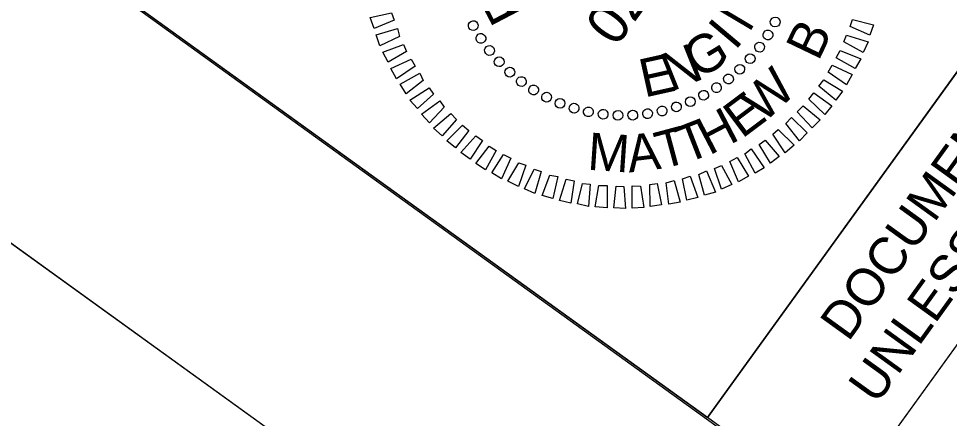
# Model space of a CAD drawing. Extents: x 2189185 to 2191058, y 386509 to 388561.
# Drawn here: x 2190081.4 to 2190218.6, y 388238.4 to 388297.3 of the extents above; entities that cross this region are included whole.
import ezdxf

# ---------------------------------------------------------------- set-up
doc = ezdxf.new("R2010")
doc.units = 0
for name, color, linetype in [('Sheet Clip Boundary CELL', 7, 'Continuous'), ('Sheet Layout Plan Border', 7, 'Continuous'), ('Sheet Plan CELL', 7, 'Continuous'), ('Sheet Plan Layout CELL', 7, 'Continuous'), ('Sheet Professional Seal CELL', 7, 'Continuous'), ('Sheet Sticker Exception Certification CELL', 7, 'Continuous')]:
    doc.layers.add(name, color=color, linetype=linetype)

msp = doc.modelspace()

# ---------------------------------------------------------------- linework, layer by layer
at = {"layer": 'Sheet Clip Boundary CELL'}
msp.add_lwpolyline([(2190166.8, 386710.01), (2190905.33, 387738.93), (2190256.9, 388232.77), (2190233.39, 388201.76), (2190061.07, 388326.03), (2189853.58, 388001.31), (2189912.61, 387915.43), (2189757.61, 387710.51), (2189654.64, 387750.49), (2189330.08, 387312.42)], close=True, dxfattribs=at)
at = {"layer": 'Sheet Layout Plan Border'}
msp.add_lwpolyline([(2190181.72, 386698.24), (2191000.63, 387833.76), (2190320.53, 388324.24), (2190209.82, 388170.73), (2190038.29, 388294.44), (2189330.08, 387312.42)], close=True, dxfattribs=at)
at = {"layer": 'Sheet Plan CELL'}
for points in [[(2190152.47, 386657.68), (2189300.84, 387271.83), (2190061.21, 388326.25), (2190182.93, 388238.48), (2190299.95, 388400.72), (2191029.88, 387874.32)], [(2190091.69, 388304.27), (2190150.21, 388385.42), (2190241.47, 388319.6), (2190182.93, 388238.48)]]:
    msp.add_lwpolyline(points, close=True, dxfattribs=at)
at = {"layer": 'Sheet Plan Layout CELL'}
for points in [[(2190209.82, 388170.73), (2190349.78, 388364.8), (2190178.26, 388488.53), (2190038.29, 388294.44)], [(2189300.84, 387271.83), (2190152.47, 386657.68), (2191029.87, 387874.31), (2190349.77, 388364.78), (2190209.82, 388170.73), (2190038.29, 388294.44)]]:
    msp.add_lwpolyline(points, close=True, dxfattribs=at)
at = {"layer": 'Sheet Professional Seal CELL'}
for p, q in [((2190148.38, 388296.22), (2190148.38, 388296.22)), ((2190192.85, 388296.77), (2190192.85, 388296.77)), ((2190191.83, 388294.85), (2190191.83, 388294.85)), ((2190149.48, 388294.32), (2190149.48, 388294.32)), ((2190150.77, 388292.53), (2190150.77, 388292.53)), ((2190190.59, 388293.03), (2190190.59, 388293.03)), ((2190152.21, 388290.94), (2190152.21, 388290.94)), ((2190189.18, 388291.34), (2190189.18, 388291.34)), ((2190153.75, 388289.39), (2190153.75, 388289.39)), ((2190187.64, 388289.8), (2190187.64, 388289.8)), ((2190155.45, 388287.99), (2190155.45, 388287.99)), ((2190186.04, 388288.36), (2190186.04, 388288.36)), ((2190157.26, 388286.74), (2190157.26, 388286.74)), ((2190184.25, 388287.06), (2190184.25, 388287.06)), ((2190159.18, 388285.72), (2190159.18, 388285.72)), ((2190182.35, 388285.97), (2190182.35, 388285.97)), ((2190161.2, 388284.76), (2190161.2, 388284.76)), ((2190163.25, 388284.02), (2190163.25, 388284.02)), ((2190178.33, 388284.24), (2190178.33, 388284.24)), ((2190180.4, 388284.97), (2190180.4, 388284.97)), ((2190165.34, 388283.5), (2190165.34, 388283.5)), ((2190167.51, 388283.17), (2190167.51, 388283.17)), ((2190169.72, 388282.99), (2190169.72, 388282.99)), ((2190171.87, 388282.98), (2190171.87, 388282.98)), ((2190174.09, 388283.23), (2190174.09, 388283.23)), ((2190176.21, 388283.61), (2190176.21, 388283.61))]:
    msp.add_line(p, q, dxfattribs=at)
for points in [[(2190136.75, 388297.03), (2190133.8, 388295.83), (2190133.17, 388297.45), (2190136.36, 388298.11)], [(2190204.28, 388297.15), (2190207.39, 388296.33), (2190206.85, 388294.81), (2190203.95, 388296.09)], [(2190137.5, 388294.64), (2190134.64, 388293.25), (2190134.09, 388294.88), (2190137.24, 388295.82)], [(2190203.41, 388294.82), (2190206.58, 388293.83), (2190205.86, 388292.25), (2190202.99, 388293.83)], [(2190138.54, 388292.41), (2190135.86, 388290.83), (2190135.04, 388292.34), (2190138.12, 388293.45)], [(2190202.45, 388292.56), (2190205.51, 388291.33), (2190204.67, 388289.91), (2190201.87, 388291.49)], [(2190139.82, 388290.25), (2190137.07, 388288.41), (2190136.26, 388289.93), (2190139.22, 388291.3)], [(2190201.29, 388290.43), (2190204.21, 388289.01), (2190203.37, 388287.51), (2190200.71, 388289.37)], [(2190141.02, 388288.16), (2190138.48, 388286.17), (2190137.6, 388287.6), (2190140.49, 388289.22)], [(2190200.03, 388288.26), (2190202.81, 388286.56), (2190201.8, 388285.25), (2190199.29, 388287.31)], [(2190142.53, 388286.14), (2190140.19, 388284.01), (2190139.05, 388285.26), (2190141.91, 388287.08)], [(2190198.58, 388286.34), (2190201.22, 388284.44), (2190200.21, 388283.13), (2190197.84, 388285.4)], [(2190144.09, 388284.21), (2190141.96, 388281.93), (2190140.78, 388283.21), (2190143.48, 388285.15)], [(2190197, 388284.4), (2190199.52, 388282.34), (2190198.31, 388281.18), (2190196.14, 388283.55)], [(2190145.93, 388282.4), (2190143.81, 388279.98), (2190142.55, 388281.13), (2190145.1, 388283.3)], [(2190195.27, 388282.69), (2190197.6, 388280.45), (2190196.44, 388279.26), (2190194.45, 388281.8)], [(2190147.73, 388280.79), (2190145.75, 388278.21), (2190144.47, 388279.26), (2190146.81, 388281.57)], [(2190149.73, 388279.29), (2190147.95, 388276.56), (2190146.57, 388277.56), (2190148.75, 388279.99)], [(2190193.33, 388280.94), (2190195.68, 388278.64), (2190194.36, 388277.49), (2190192.52, 388280.24)], [(2190151.78, 388277.86), (2190150.21, 388274.99), (2190148.77, 388275.91), (2190150.75, 388278.49)], [(2190191.4, 388279.38), (2190193.48, 388276.95), (2190192.17, 388275.99), (2190190.5, 388278.73)], [(2190153.91, 388276.7), (2190152.57, 388273.66), (2190151.11, 388274.53), (2190152.82, 388277.24)], [(2190189.36, 388278.08), (2190191.24, 388275.3), (2190189.93, 388274.52), (2190188.4, 388277.35)], [(2190156.12, 388275.67), (2190155.04, 388272.55), (2190153.49, 388273.31), (2190155.09, 388276.04)], [(2190184.99, 388275.62), (2190186.51, 388272.85), (2190184.95, 388272.13), (2190183.95, 388275.2)], [(2190187.27, 388276.81), (2190188.93, 388274.07), (2190187.46, 388273.22), (2190186.18, 388276.24)], [(2190158.41, 388274.75), (2190157.47, 388271.48), (2190155.96, 388272.2), (2190157.36, 388275.08)], [(2190160.83, 388273.99), (2190160.1, 388270.76), (2190158.52, 388271.22), (2190159.68, 388274.2)], [(2190182.76, 388274.82), (2190184.09, 388271.71), (2190182.47, 388271.27), (2190181.63, 388274.28)], [(2190163.26, 388273.35), (2190162.75, 388270.08), (2190161.07, 388270.49), (2190162.08, 388273.59)], [(2190165.59, 388272.9), (2190165.37, 388269.61), (2190163.73, 388269.99), (2190164.47, 388272.97)], [(2190175.5, 388272.97), (2190176.15, 388269.85), (2190174.47, 388269.58), (2190174.41, 388272.83)], [(2190177.97, 388273.4), (2190178.88, 388270.22), (2190177.21, 388269.95), (2190176.81, 388273.07)], [(2190180.34, 388274.04), (2190181.49, 388270.93), (2190179.84, 388270.52), (2190179.22, 388273.68)], [(2190168.13, 388272.67), (2190168.13, 388269.41), (2190166.35, 388269.52), (2190166.91, 388272.69)], [(2190170.56, 388272.53), (2190170.83, 388269.31), (2190169.1, 388269.39), (2190169.44, 388272.59)], [(2190173.02, 388272.6), (2190173.5, 388269.42), (2190171.79, 388269.36), (2190171.8, 388272.62)]]:
    msp.add_lwpolyline(points, close=True, dxfattribs=at)
for centre, major_axis in [((2190192.88, 388296.77), (0.643, -0.325)), ((2190148.39, 388296.23), (-0.635, -0.34)), ((2190149.51, 388294.35), (-0.602, -0.394)), ((2190191.81, 388294.86), (0.612, -0.379)), ((2190190.58, 388293.06), (0.577, -0.431)), ((2190150.78, 388292.57), (-0.566, -0.445)), ((2190189.19, 388291.36), (0.537, -0.48)), ((2190152.21, 388290.91), (-0.525, -0.493)), ((2190153.78, 388289.38), (-0.48, -0.537)), ((2190187.66, 388289.8), (0.493, -0.525)), ((2190155.47, 388288), (-0.431, -0.577)), ((2190184.23, 388287.09), (0.394, -0.602)), ((2190186, 388288.37), (0.445, -0.566)), ((2190157.28, 388286.76), (-0.379, -0.612)), ((2190182.34, 388285.98), (0.34, -0.635)), ((2190159.19, 388285.69), (-0.325, -0.643)), ((2190161.18, 388284.79), (-0.267, -0.669)), ((2190180.37, 388285.03), (0.284, -0.662)), ((2190163.24, 388284.07), (-0.208, -0.689)), ((2190165.36, 388283.53), (-0.147, -0.705)), ((2190167.52, 388283.18), (-0.085, -0.715)), ((2190174.07, 388283.26), (0.103, -0.713)), ((2190176.22, 388283.66), (0.164, -0.701)), ((2190178.33, 388284.26), (0.225, -0.684)), ((2190169.71, 388283.01), (-0.023, -0.72)), ((2190171.89, 388283.04), (0.04, -0.719))]:
    msp.add_ellipse(centre, major_axis=major_axis, ratio=0.999708, dxfattribs=at)
at = {"layer": 'Sheet Sticker Exception Certification CELL'}
for p, q in [((2190182.93, 388238.48), (2190299.94, 388400.73)), ((2190182.93, 388238.48), (2190299.94, 388400.73)), ((2190319, 388386.98), (2190201.99, 388224.74)), ((2190319, 388386.98), (2190201.99, 388224.74)), ((2190201.99, 388224.74), (2190182.93, 388238.48)), ((2190201.99, 388224.74), (2190182.93, 388238.48))]:
    msp.add_line(p, q, dxfattribs=at)

# ---------------------------------------------------------------- texts
at = {"layer": 'Sheet Professional Seal CELL'}
for s, height, rotation, p in [('027771', 5.998, 54.2018, (2190169.44, 388292.93)), ('N', 5.64, 59.2582, (2190189.04, 388295.07)), ('P', 5.64, 117.6007, (2190156.45, 388298.36)), ('I', 5.64, 49.903, (2190186.96, 388292.45)), ('B', 5.5, 64.4224, (2190199.24, 388290.87)), ('G', 5.64, 31.1921, (2190181.59, 388288.24)), ('N', 5.64, 21.8358, (2190177.54, 388286.48)), ('E', 5.64, 12.4787, (2190173.59, 388285.62)), ('W', 5.5, 43.3711, (2190191.14, 388281.69)), ('E', 5.5, 36.7881, (2190187.98, 388279.5)), ('H', 5.5, 27.5433, (2190183.16, 388277.06)), ('T', 5.5, 21.2466, (2190179.69, 388275.86)), ('T', 5.5, 14.9498, (2190176.1, 388275.04)), ('M', 5.5, 356.0881, (2190165.12, 388275.01)), ('A', 5.5, 6.764, (2190171.34, 388274.58))]:
    msp.add_text(s, height=height, rotation=rotation, dxfattribs=at).set_placement(p)
at = {"layer": 'Sheet Sticker Exception Certification CELL'}
for s, p in [('DOCUMENT NOT CONSIDERED FINAL', (2190203.65, 388249.52)), ('DOCUMENT NOT CONSIDERED FINAL', (2190203.65, 388249.52)), ('UNLESS ALL SIGNATURES COMPLETED', (2190207.82, 388240.26)), ('UNLESS ALL SIGNATURES COMPLETED', (2190207.82, 388240.26))]:
    msp.add_text(s, height=5.5, rotation=54.2018, dxfattribs=at).set_placement(p)

doc.saveas('drawing.dxf')
